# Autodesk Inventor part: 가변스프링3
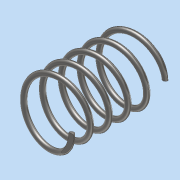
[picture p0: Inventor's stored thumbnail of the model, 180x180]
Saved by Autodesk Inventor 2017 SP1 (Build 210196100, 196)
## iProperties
Part Number: 가변스프링3
Material: 강철, 연강
Document SubType Name: Modeling
Designer: MRC
Density: 7.85 g/cm^3
Appearance: 반연마
Mass: 8.42324 g
Surface Area: 21.7217 cm^2
Volume: 1.07302 cm^3
Author: MRC
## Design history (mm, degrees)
sketch "스케치1"
  geometry: L1 (0, 0)-(0, 36.411); L2 (0, 0)-(11, 0); L3 (0, 36.411)-(11, 36.411); C1 r 1 at (11, 0)
  constraints: 6 end point, 2 horizontal, 1 centre point, 1 coincident, 1 vertical
  dimensions: "d0" = 36.4112 distance of L1.start L1.end (derived); "d1" = 2 diameter of C1; "d2" = 22 diameter of L2.end L1
feature "코일1" sketch "스케치1" pitch "d3" = 10; turns "d5" = 5; dims "d4" = 36.4112 (= d0), "d6" = 0, angle "d7" = 90 deg, angle "d8" = 90 deg, "d9" = 0, "d10" = 0
sketch "스케치2"
  geometry: L1 (15, 0)-(-15, 0); L2 (-15, 0)-(-15, 36.411); L3 (-15, 36.411)-(15, 36.411); L4 (15, 36.411)-(15, 0); 1 further point
  constraints: 8 end point, 2 parallel, 1 horizontal, 1 midpoint, 1 perpendicular
  dimensions: "d11" = 36.4112 distance of L3.end L1.start (= d0); "d12" = 30 distance between parallel lines of L2 L4; "d13" = 15 distance from line of point (0, 0) L4 (= 0.5 x d12)
extrude "돌출1" sketch "스케치2" stored distance "d14" = 30; taper "d15" = 0 deg
node "솔리드1"
